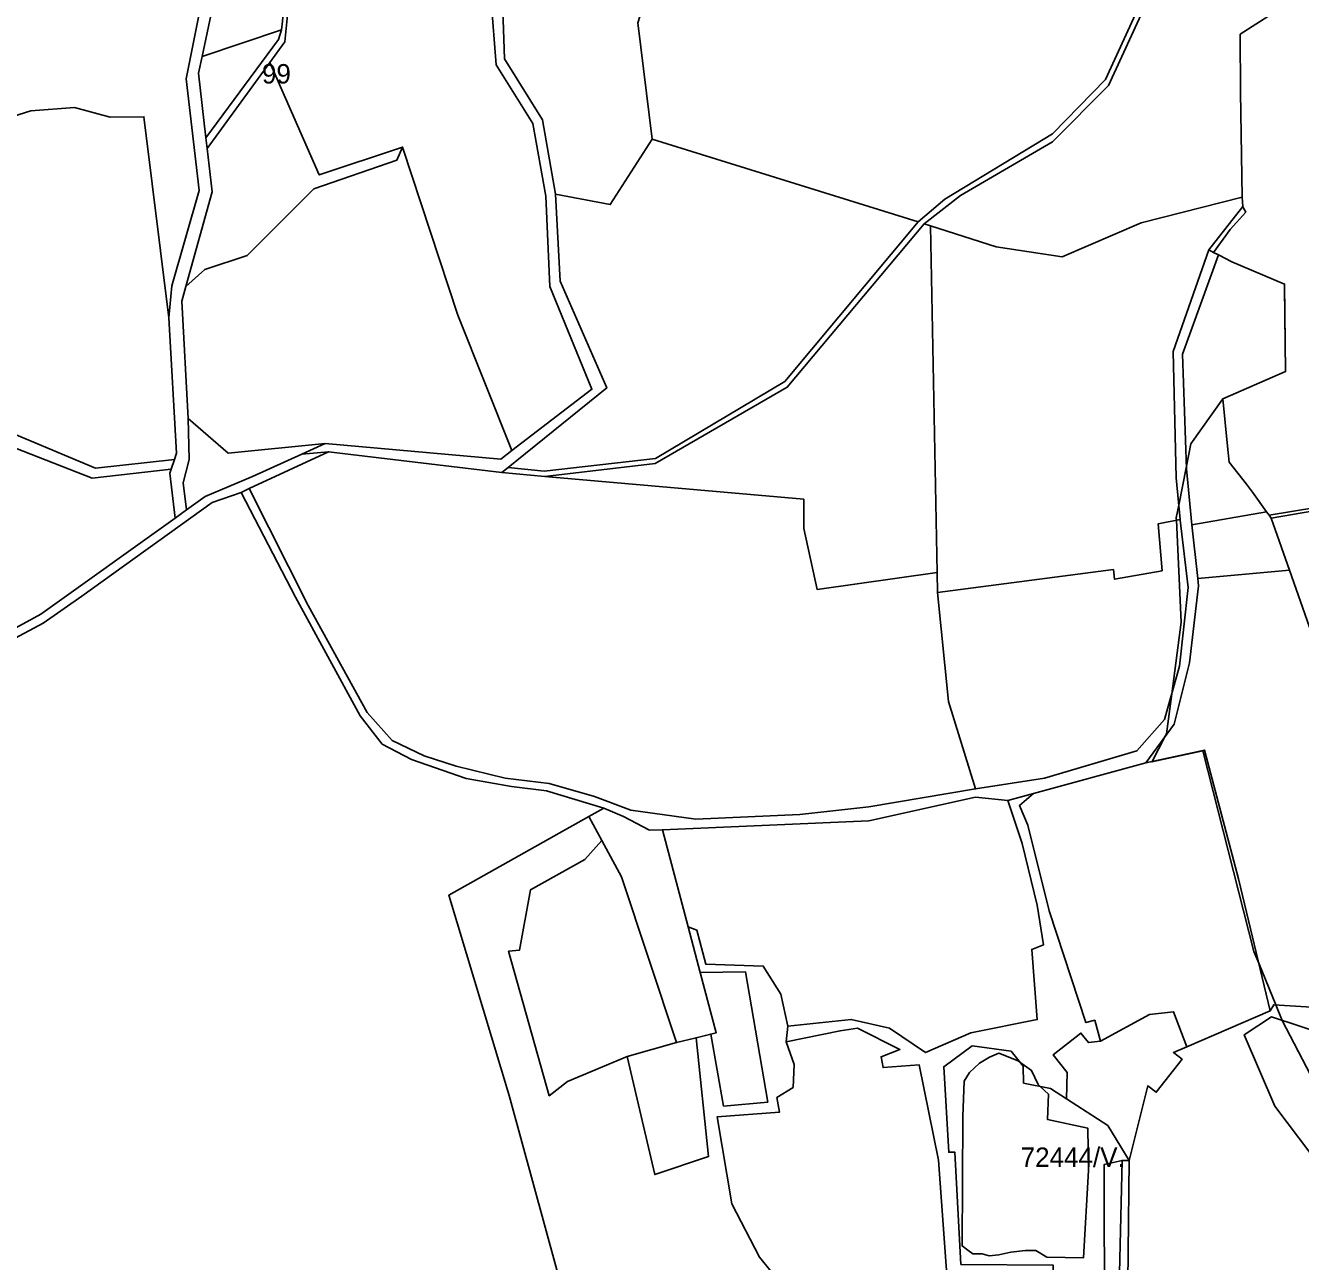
# Model space of a CAD drawing. Extents: x -502026 to -497664, y -1143484 to -1138019.
# Drawn here: x -499334 to -498809, y -1143009 to -1142500 of the extents above; entities that cross this region are included whole.
import ezdxf

# ---------------------------------------------------------------- set-up
doc = ezdxf.new("R2010")
doc.units = 0
for name, color, linetype in [('37', 7, 'Continuous'), ('43', 7, 'Continuous'), ('55', 7, 'Continuous'), ('62', 7, 'Continuous')]:
    doc.layers.add(name, color=color, linetype=linetype)

msp = doc.modelspace()

# ---------------------------------------------------------------- linework, layer by layer
at = {"layer": '37'}
msp.add_lwpolyline([(-498718.92, -1142695.09), (-498713.81, -1142703.58), (-498705.09, -1142704.42), (-498696.25, -1142725.42), (-498729.58, -1142732.34), (-498768.81, -1142745.89), (-498802.13, -1142758.2), (-498813.95, -1142724.49), (-498821.39, -1142703.09), (-498781.57, -1142696.34), (-498742.86, -1142693.2)], close=True, dxfattribs=at)
at = {"layer": '43'}
for points in [[(-499186.12, -1142301.39), (-499193.9, -1142349.92), (-499212.53, -1142388.21), (-499216.16, -1142395.67), (-499227.31, -1142507.01), (-499233.5, -1142515.51), (-499259.3, -1142550.94), (-499259.79, -1142546.61), (-499229.88, -1142506.05), (-499228.62, -1142502.13), (-499228.3, -1142498.46), (-499219.13, -1142394.71), (-499215.59, -1142387.65), (-499195.99, -1142348.47), (-499191.48, -1142319.08), (-499188.68, -1142300.88)], [(-499063.88, -1142441.35), (-499082.12, -1142499.27), (-499076.16, -1142547.04), (-499093.38, -1142574.06), (-499115.92, -1142569.72), (-499121.25, -1142539.11), (-499136.98, -1142514.08), (-499138.35, -1142473.56), (-499129.3, -1142435.22)], [(-499259.79, -1142546.61), (-499262.83, -1142519.94), (-499261.37, -1142513.05), (-499228.62, -1142502.13), (-499229.88, -1142506.05)], [(-499178.85, -1142550.33), (-499181.2, -1142555.78), (-499215.39, -1142567.55), (-499242.77, -1142595.06), (-499260.23, -1142600.76), (-499268.02, -1142607.75), (-499257.26, -1142568.79), (-499259.3, -1142550.94), (-499233.5, -1142515.51), (-499213.16, -1142561.85)], [(-498966.7, -1142581.15), (-499021.62, -1142646.92), (-499074.76, -1142678.52), (-499120.59, -1142683.79), (-499135.36, -1142682.28), (-499094.83, -1142649.52), (-499114.07, -1142605.54), (-499115.92, -1142569.72), (-499093.38, -1142574.06), (-499076.16, -1142547.04)], [(-499133.88, -1142675.3), (-499138.47, -1142678.81), (-499210.68, -1142672.39), (-499250.66, -1142676.39), (-499267.09, -1142662.15), (-499269.7, -1142613.84), (-499268.02, -1142607.75), (-499260.23, -1142600.76), (-499242.77, -1142595.06), (-499215.39, -1142567.55), (-499181.2, -1142555.78), (-499178.85, -1142550.33), (-499156.06, -1142619.54)], [(-498833.12, -1142574.8), (-498847.11, -1142592.66), (-498861.74, -1142634.49), (-498860.56, -1142686.49), (-498858.93, -1142703.74), (-498867.93, -1142705.43), (-498866.32, -1142724.83), (-498885.89, -1142728.3), (-498886.33, -1142724.35), (-498958.76, -1142733.81), (-498958.86, -1142725.52), (-498961.6, -1142582.77), (-498934.61, -1142591.49), (-498907.39, -1142595.5), (-498874.99, -1142581.57), (-498833.33, -1142570.94)], [(-498961.6, -1142582.77), (-498958.86, -1142725.52), (-499008.31, -1142732.5), (-499013.79, -1142707.36), (-499013.79, -1142695.36), (-499120.39, -1142685.99), (-499074.92, -1142680.62), (-499020.57, -1142649.24), (-498964.28, -1142581.91)], [(-498823.31, -1142700.5), (-498854.02, -1142705.83), (-498856.28, -1142682.79), (-498857.89, -1142635.65), (-498843.16, -1142594.79), (-498837.62, -1142597.55), (-498815.89, -1142606.77), (-498815.49, -1142642.8), (-498841.37, -1142654.07), (-498839.34, -1142673.46), (-498838.65, -1142680.03), (-498831.61, -1142689.17), (-498829.05, -1142692.5)], [(-499210.68, -1142672.39), (-499220.38, -1142676.8), (-499240.61, -1142685.99), (-499260.08, -1142694.22), (-499267.81, -1142699.76), (-499269.13, -1142688.66), (-499266.62, -1142679.06), (-499267.09, -1142662.15), (-499250.66, -1142676.39)], [(-499274.07, -1142683.02), (-499274.62, -1142684.66), (-499272.44, -1142703.08), (-499327.73, -1142742.72), (-499360.83, -1142760.7), (-499390.53, -1142787.67), (-499419.09, -1142808.73), (-499455.39, -1142717), (-499437.6, -1142711.34), (-499398.67, -1142683.09), (-499357.32, -1142673.8), (-499341.27, -1142673.06), (-499306.6, -1142686.61)], [(-499137.98, -1142684.28), (-499120.39, -1142685.99), (-499013.79, -1142695.36), (-499013.79, -1142707.36), (-499008.31, -1142732.5), (-498958.86, -1142725.52), (-498958.76, -1142733.81), (-498954.16, -1142778.67), (-498943.09, -1142814.6), (-498986.95, -1142821.98), (-499015.32, -1142825.12), (-499058.16, -1142827.09), (-499084.93, -1142823.39), (-499099.91, -1142817.8), (-499118.5, -1142812.36), (-499136.71, -1142810.13), (-499156.79, -1142805.27), (-499170.03, -1142800.96), (-499183.16, -1142794.64), (-499193.44, -1142783.11), (-499217.78, -1142739.04), (-499242.02, -1142690.97), (-499209.32, -1142675.8)], [(-498943.09, -1142814.6), (-498954.16, -1142778.67), (-498958.76, -1142733.81), (-498886.33, -1142724.35), (-498885.89, -1142728.3), (-498866.32, -1142724.83), (-498867.93, -1142705.43), (-498858.93, -1142703.74), (-498858.92, -1142703.91), (-498855.63, -1142731.69), (-498859.19, -1142764.04), (-498865.29, -1142786.09), (-498876.67, -1142799.01), (-498914.66, -1142810.14)], [(-498822.28, -1142701.93), (-498821.39, -1142703.09), (-498813.95, -1142724.49), (-498851.63, -1142727.92), (-498854.02, -1142705.83), (-498823.31, -1142700.5)], [(-498802.13, -1142758.2), (-498801.6, -1142759.91), (-498804.77, -1142761.15), (-498804.49, -1142762.6), (-498798.94, -1142790.97), (-498797.52, -1142794.75), (-498793.96, -1142803.22), (-498792.37, -1142807.01), (-498789.64, -1142827.96), (-498780.24, -1142890.32), (-498780.62, -1142901.94), (-498800.33, -1142904.75), (-498820.36, -1142903.49), (-498821.78, -1142906.01), (-498834.84, -1142851.68), (-498848.87, -1142798.61), (-498873.05, -1142803.85), (-498861.35, -1142788.01), (-498855.04, -1142762.74), (-498851.29, -1142731.06), (-498851.63, -1142727.92), (-498813.95, -1142724.49)], [(-498821.78, -1142906.01), (-498856.2, -1142920.76), (-498861.62, -1142906.39), (-498871.46, -1142907.52), (-498891.69, -1142918.55), (-498894.02, -1142909.9), (-498897.63, -1142910.86), (-498912.8, -1142864.76), (-498921.5, -1142829.55), (-498925.04, -1142821.48), (-498919.17, -1142816.54), (-498873.05, -1142803.85), (-498848.87, -1142798.61), (-498834.84, -1142851.68)], [(-498929.8, -1142819.46), (-498923.87, -1142837.05), (-498917.77, -1142862.47), (-498915.09, -1142878.85), (-498919.94, -1142880.69), (-498917.69, -1142909.62), (-498945.06, -1142915.09), (-498963.74, -1142923.17), (-498978.52, -1142913.19), (-498994.26, -1142909.54), (-499020.31, -1142912.27), (-499023.15, -1142899.13), (-499030.46, -1142887.55), (-499054.13, -1142886.82), (-499057.74, -1142872.74), (-499061.34, -1142871.38), (-499071.91, -1142831.44), (-498987, -1142827.81), (-498943.09, -1142818.07)], [(-499071.91, -1142831.44), (-499061.34, -1142871.38), (-499056.35, -1142890.25), (-499049.79, -1142915.04), (-499052.02, -1142915.59), (-499058.09, -1142917.09), (-499066.15, -1142919.07), (-499088.81, -1142850.86), (-499096.86, -1142835.91), (-499102.19, -1142826.02), (-499096.01, -1142822.55), (-499087.9, -1142825.99), (-499077.3, -1142831.66)], [(-499066.15, -1142919.07), (-499086.46, -1142924.75), (-499110.93, -1142935.08), (-499118.52, -1142940.96), (-499135.24, -1142881.44), (-499130.78, -1142881.04), (-499126.22, -1142856.13), (-499103.89, -1142843.73), (-499096.86, -1142835.91), (-499088.81, -1142850.86)], [(-499052.02, -1142915.59), (-499049.79, -1142915.04), (-499056.35, -1142890.25), (-499037.77, -1142889.87), (-499028.6, -1142943.57), (-499046.78, -1142945.23)], [(-498856.2, -1142920.76), (-498861.68, -1142923.11), (-498858.09, -1142925.91), (-498868.71, -1142939.54), (-498872.18, -1142936.84), (-498879.9, -1142967.62), (-498888.66, -1142953.18), (-498905.65, -1142942.19), (-498905.43, -1142931.44), (-498911.17, -1142924.16), (-498899.72, -1142915.13), (-498896.61, -1142919.07), (-498891.69, -1142918.55), (-498871.46, -1142907.52), (-498861.62, -1142906.39)], [(-498787.24, -1142934.61), (-498791.45, -1142942.27), (-498794.1, -1142951.32), (-498787.26, -1142964.11), (-498768.58, -1142992.66), (-498775.87, -1143002.39), (-498784.58, -1142992.53), (-498790.85, -1142993.81), (-498800.06, -1142971.66), (-498819.9, -1142945.25), (-498832.51, -1142915.83), (-498821.31, -1142908.5), (-498799.17, -1142915.67), (-498794.56, -1142926.55)], [(-498978.38, -1143067.64), (-498985.62, -1143037.13), (-499006.08, -1143039.33), (-499008.67, -1143036.14), (-499031.92, -1143007.46), (-499043.31, -1142985.4), (-499049.39, -1142949.62), (-499023.78, -1142947.73), (-499024.81, -1142941.68), (-499018.17, -1142937.49), (-499017.78, -1142928.08), (-499021.01, -1142918.81), (-498998.8, -1142914.2), (-498991.7, -1142913.18), (-498974.23, -1142921.89), (-498981.94, -1142924.88), (-498981.14, -1142929.36), (-498966.23, -1142928.26), (-498958.26, -1142967.52), (-498953.28, -1143037.42), (-498969.24, -1143059.9)], [(-499086.46, -1142924.75), (-499066.15, -1142919.07), (-499058.09, -1142917.09), (-499052.95, -1142965.98), (-499075.08, -1142973.42)], [(-498905.65, -1142942.19), (-498888.66, -1142953.18), (-498879.9, -1142967.62), (-498882.81, -1142967.59), (-498890.11, -1142969.25), (-498890.07, -1143037.19), (-498911.43, -1143041.96), (-498911.18, -1143010.7), (-498949.07, -1143010.39), (-498951.56, -1142964.2), (-498954.14, -1142964.19), (-498956.19, -1142928.99), (-498944.46, -1142920.41), (-498928.45, -1142922.62), (-498923.55, -1142928.78), (-498923.32, -1142935.75), (-498912.27, -1142937.91)], [(-498879.9, -1142967.62), (-498880.64, -1143042.87), (-498876.46, -1143077.46), (-498889.09, -1143081.57), (-498897.61, -1143079.07), (-498898.74, -1143044.93), (-498884.54, -1143042.85), (-498882.81, -1142967.59)]]:
    msp.add_lwpolyline(points, close=True, dxfattribs=at)
for points in [[(-499143.8, -1142472.44), (-499140.33, -1142516.56), (-499125.21, -1142540.6), (-499119.89, -1142570.59), (-499118.28, -1142607.77), (-499100.94, -1142650.06), (-499133.88, -1142675.3), (-499156.06, -1142619.54), (-499178.85, -1142550.33), (-499213.16, -1142561.85), (-499233.5, -1142515.51), (-499227.31, -1142507.01), (-499216.16, -1142395.67)], [(-499255.77, -1142460.92), (-499267.85, -1142522.22), (-499262.59, -1142568.19), (-499273.82, -1142607.44), (-499275.01, -1142620.71), (-499285.33, -1142537.9), (-499299.13, -1142538.05), (-499313.87, -1142534.09), (-499331.89, -1142535.47), (-499383.94, -1142551.77)], [(-499228.3, -1142498.46), (-499228.62, -1142502.13), (-499261.37, -1142513.05), (-499250.45, -1142461.57)], [(-498866.58, -1142472.13), (-498889.62, -1142522.6), (-498911.44, -1142544.84), (-498955.78, -1142571.85), (-498966.7, -1142581.15), (-499076.16, -1142547.04), (-499082.12, -1142499.27)], [(-498814.79, -1142491.58), (-498834.12, -1142503.88), (-498834.03, -1142527.73), (-498833.33, -1142570.94), (-498874.99, -1142581.57), (-498907.39, -1142595.5), (-498934.61, -1142591.49), (-498961.6, -1142582.77), (-498964.28, -1142581.91), (-498949.34, -1142570.24), (-498911.44, -1142548.18), (-498888.32, -1142524.95), (-498863.98, -1142471.76)], [(-499383.94, -1142551.77), (-499331.89, -1142535.47), (-499313.87, -1142534.09), (-499299.13, -1142538.05), (-499285.33, -1142537.9), (-499275.01, -1142620.71), (-499271.87, -1142676.44), (-499272.71, -1142678.95), (-499305.23, -1142682.61), (-499341.21, -1142667.43)], [(-499357.89, -1142763.04), (-499326.71, -1142746.41), (-499310.8, -1142735.23), (-499257.26, -1142696.67), (-499245.27, -1142692.58), (-499222.99, -1142735.63), (-499196.34, -1142784.58), (-499187.21, -1142796.15), (-499175.15, -1142802.55), (-499152.7, -1142810.27), (-499134.05, -1142813.56), (-499119.61, -1142815.39), (-499096.01, -1142822.55), (-499102.19, -1142826.02), (-499159.82, -1142858.36), (-499135.06, -1142940.83), (-499101.04, -1143065.28)], [(-498953.28, -1143037.42), (-498958.26, -1142967.52), (-498966.23, -1142928.26), (-498981.14, -1142929.36), (-498981.94, -1142924.88), (-498974.23, -1142921.89), (-498991.7, -1142913.18), (-498998.8, -1142914.2), (-499021.01, -1142918.81), (-499020.31, -1142912.27), (-498994.26, -1142909.54), (-498978.52, -1142913.19), (-498963.74, -1142923.17), (-498945.06, -1142915.09), (-498917.69, -1142909.62), (-498919.94, -1142880.69), (-498915.09, -1142878.85), (-498917.77, -1142862.47), (-498923.87, -1142837.05), (-498929.8, -1142819.46), (-498919.17, -1142816.54), (-498925.04, -1142821.48), (-498921.5, -1142829.55), (-498912.8, -1142864.76), (-498897.63, -1142910.86), (-498894.02, -1142909.9), (-498891.69, -1142918.55), (-498896.61, -1142919.07), (-498899.72, -1142915.13), (-498911.17, -1142924.16), (-498905.43, -1142931.44), (-498905.65, -1142942.19), (-498912.27, -1142937.91), (-498923.32, -1142935.75), (-498923.55, -1142928.78), (-498928.45, -1142922.62), (-498944.46, -1142920.41), (-498956.19, -1142928.99), (-498954.14, -1142964.19), (-498951.56, -1142964.2), (-498949.07, -1143010.39)], [(-499101.04, -1143065.28), (-499135.06, -1142940.83), (-499159.82, -1142858.36), (-499102.19, -1142826.02), (-499096.86, -1142835.91), (-499103.89, -1142843.73), (-499126.22, -1142856.13), (-499130.78, -1142881.04), (-499135.24, -1142881.44), (-499118.52, -1142940.96), (-499110.93, -1142935.08), (-499086.46, -1142924.75), (-499075.08, -1142973.42), (-499052.95, -1142965.98), (-499058.09, -1142917.09), (-499052.02, -1142915.59), (-499046.78, -1142945.23), (-499028.6, -1142943.57), (-499037.77, -1142889.87), (-499056.35, -1142890.25), (-499061.34, -1142871.38), (-499057.74, -1142872.74), (-499054.13, -1142886.82), (-499030.46, -1142887.55), (-499023.15, -1142899.13), (-499020.31, -1142912.27), (-499021.01, -1142918.81), (-499017.78, -1142928.08), (-499018.17, -1142937.49), (-499024.81, -1142941.68), (-499023.78, -1142947.73), (-499049.39, -1142949.62), (-499043.31, -1142985.4), (-499031.92, -1143007.46), (-499008.67, -1143036.14)], [(-498880.64, -1143042.87), (-498879.9, -1142967.62), (-498872.18, -1142936.84), (-498868.71, -1142939.54), (-498858.09, -1142925.91), (-498861.68, -1142923.11), (-498856.2, -1142920.76), (-498821.78, -1142906.01), (-498820.36, -1142903.49), (-498800.33, -1142904.75)], [(-498799.17, -1142915.67), (-498821.31, -1142908.5), (-498832.51, -1142915.83), (-498819.9, -1142945.25), (-498800.06, -1142971.66)], [(-498890.07, -1143037.19), (-498890.11, -1142969.25), (-498882.81, -1142967.59), (-498884.54, -1143042.85)]]:
    msp.add_lwpolyline(points, dxfattribs=at)
at = {"layer": '55'}
for points in [[(-499250.45, -1142461.57), (-499261.37, -1142513.05), (-499262.83, -1142519.94), (-499259.79, -1142546.61), (-499259.3, -1142550.94), (-499257.26, -1142568.79), (-499268.02, -1142607.75), (-499269.7, -1142613.84), (-499267.09, -1142662.15), (-499266.62, -1142679.06), (-499269.13, -1142688.66), (-499267.81, -1142699.76), (-499272.44, -1142703.08), (-499274.62, -1142684.66), (-499274.07, -1142683.02), (-499272.71, -1142678.95), (-499271.87, -1142676.44), (-499275.01, -1142620.71), (-499273.82, -1142607.44), (-499262.59, -1142568.19), (-499267.85, -1142522.22), (-499255.77, -1142460.92)], [(-499138.35, -1142473.56), (-499136.98, -1142514.08), (-499121.25, -1142539.11), (-499115.92, -1142569.72), (-499114.07, -1142605.54), (-499094.83, -1142649.52), (-499135.36, -1142682.28), (-499137.98, -1142684.28), (-499209.32, -1142675.8), (-499220.38, -1142676.8), (-499210.68, -1142672.39), (-499138.47, -1142678.81), (-499133.88, -1142675.3), (-499100.94, -1142650.06), (-499118.28, -1142607.77), (-499119.89, -1142570.59), (-499125.21, -1142540.6), (-499140.33, -1142516.56), (-499143.8, -1142472.44)], [(-498863.98, -1142471.76), (-498888.32, -1142524.95), (-498911.44, -1142548.18), (-498949.34, -1142570.24), (-498964.28, -1142581.91), (-499020.57, -1142649.24), (-499074.92, -1142680.62), (-499120.39, -1142685.99), (-499137.98, -1142684.28), (-499135.36, -1142682.28), (-499120.59, -1142683.79), (-499074.76, -1142678.52), (-499021.62, -1142646.92), (-498966.7, -1142581.15), (-498955.78, -1142571.85), (-498911.44, -1142544.84), (-498889.62, -1142522.6), (-498866.58, -1142472.13)], [(-499341.21, -1142667.43), (-499305.23, -1142682.61), (-499272.71, -1142678.95), (-499274.07, -1142683.02), (-499306.6, -1142686.61), (-499341.27, -1142673.06)], [(-499360.83, -1142760.7), (-499327.73, -1142742.72), (-499272.44, -1142703.08), (-499267.81, -1142699.76), (-499260.08, -1142694.22), (-499240.61, -1142685.99), (-499220.38, -1142676.8), (-499209.32, -1142675.8), (-499242.02, -1142690.97), (-499245.27, -1142692.58), (-499257.26, -1142696.67), (-499310.8, -1142735.23), (-499326.71, -1142746.41), (-499357.89, -1142763.04)]]:
    msp.add_lwpolyline(points, dxfattribs=at)
for points in [[(-498845.21, -1142593.77), (-498847.11, -1142592.66), (-498833.12, -1142574.8), (-498832.91, -1142575.2), (-498831.91, -1142577.12), (-498838.27, -1142584.27)], [(-498845.21, -1142593.77), (-498843.16, -1142594.79), (-498857.89, -1142635.65), (-498856.28, -1142682.79), (-498854.02, -1142705.83), (-498851.63, -1142727.92), (-498851.29, -1142731.06), (-498855.04, -1142762.74), (-498861.35, -1142788.01), (-498873.05, -1142803.85), (-498919.17, -1142816.54), (-498929.8, -1142819.46), (-498943.09, -1142818.07), (-498987, -1142827.81), (-499071.91, -1142831.44), (-499077.3, -1142831.66), (-499087.9, -1142825.99), (-499096.01, -1142822.55), (-499119.61, -1142815.39), (-499134.05, -1142813.56), (-499152.7, -1142810.27), (-499175.15, -1142802.55), (-499187.21, -1142796.15), (-499196.34, -1142784.58), (-499222.99, -1142735.63), (-499245.27, -1142692.58), (-499242.02, -1142690.97), (-499217.78, -1142739.04), (-499193.44, -1142783.11), (-499183.16, -1142794.64), (-499170.03, -1142800.96), (-499156.79, -1142805.27), (-499136.71, -1142810.13), (-499118.5, -1142812.36), (-499099.91, -1142817.8), (-499084.93, -1142823.39), (-499058.16, -1142827.09), (-499015.32, -1142825.12), (-498986.95, -1142821.98), (-498943.09, -1142814.6), (-498914.66, -1142810.14), (-498876.67, -1142799.01), (-498865.29, -1142786.09), (-498859.19, -1142764.04), (-498855.63, -1142731.69), (-498858.92, -1142703.91), (-498858.93, -1142703.74), (-498860.56, -1142686.49), (-498861.74, -1142634.49), (-498847.11, -1142592.66)], [(-498549.19, -1142729.61), (-498574.36, -1142721.48), (-498608.31, -1142711.62), (-498634.43, -1142703.56), (-498668.99, -1142697.77), (-498705.26, -1142696.31), (-498718.92, -1142695.09), (-498742.86, -1142693.2), (-498781.57, -1142696.34), (-498821.39, -1142703.09), (-498822.28, -1142701.93), (-498783.08, -1142695.45), (-498762.56, -1142693.69), (-498743.39, -1142692.1), (-498707.76, -1142694.47), (-498691.29, -1142695.25), (-498668.23, -1142696.44), (-498646.3, -1142699.53), (-498632.79, -1142702.37), (-498619.48, -1142705.38), (-498603.94, -1142709.81), (-498571.77, -1142720.19), (-498550.49, -1142727.91), (-498549.47, -1142728.28)]]:
    msp.add_lwpolyline(points, close=True, dxfattribs=at)
at = {"layer": '62'}
for points in [[(-498814.79, -1142491.58), (-498834.12, -1142503.88), (-498834.03, -1142527.73), (-498833.33, -1142570.94), (-498833.12, -1142574.8), (-498832.91, -1142575.2), (-498831.91, -1142577.12), (-498838.27, -1142584.27), (-498845.21, -1142593.77), (-498843.16, -1142594.79), (-498837.62, -1142597.55), (-498815.89, -1142606.77), (-498815.88, -1142608.03), (-498815.49, -1142642.8), (-498841.37, -1142654.07), (-498854.5, -1142672.5), (-498856.32, -1142681.73), (-498859.49, -1142697.85), (-498860.5, -1142703), (-498860.45, -1142704.02), (-498858.5, -1142746), (-498862.34, -1142775.41), (-498864.5, -1142792), (-498864.99, -1142792.93), (-498870.38, -1142803.27), (-498870.5, -1142803.5), (-498849.5, -1142799), (-498828.5, -1142881.5), (-498826.49, -1142886.4), (-498819.47, -1142903.54), (-498816.85, -1142909.94), (-498805.26, -1142932.33)], [(-498805.26, -1142932.33), (-498816.85, -1142909.94), (-498819.47, -1142903.54), (-498826.49, -1142886.4), (-498828.5, -1142881.5), (-498849.5, -1142799), (-498870.5, -1142803.5), (-498870.38, -1142803.27), (-498864.99, -1142792.93), (-498864.5, -1142792), (-498862.34, -1142775.41), (-498858.5, -1142746), (-498860.45, -1142704.02), (-498860.5, -1142703), (-498859.49, -1142697.85), (-498856.32, -1142681.73), (-498854.5, -1142672.5), (-498841.37, -1142654.07), (-498839.34, -1142673.46), (-498838.65, -1142680.03), (-498831.61, -1142689.17), (-498829.05, -1142692.5), (-498823.31, -1142700.5), (-498822.28, -1142701.93), (-498783.08, -1142695.45)]]:
    msp.add_lwpolyline(points, dxfattribs=at)
for points in [[(-498896.6, -1142971.8), (-498898.7, -1143007.7), (-498913.7, -1143007.4), (-498918.3, -1143004.7), (-498922.5, -1143004.7), (-498928.5, -1143005.3), (-498933.5, -1143006.4), (-498937.5, -1143006.8), (-498940.31, -1143006.08), (-498944.2, -1143006), (-498946.3, -1143004.5), (-498948.6, -1143002.8), (-498948.3, -1142949.5), (-498947.7, -1142934.9), (-498945.6, -1142931.4), (-498941.5, -1142927.6), (-498937.3, -1142925.1), (-498933.5, -1142923.4), (-498925.6, -1142926.6), (-498924.89, -1142927.09), (-498920, -1142930.5), (-498917.3, -1142936.3), (-498916.44, -1142937.09), (-498913.03, -1142940.26), (-498913.5, -1142950.7), (-498896.9, -1142954.3)], [(-498896.6, -1142971.8), (-498896.9, -1142954.3), (-498913.5, -1142950.7), (-498913.03, -1142940.26), (-498916.44, -1142937.09), (-498917.3, -1142936.3), (-498920, -1142930.5), (-498924.89, -1142927.09), (-498925.6, -1142926.6), (-498933.5, -1142923.4), (-498937.3, -1142925.1), (-498941.5, -1142927.6), (-498945.6, -1142931.4), (-498947.7, -1142934.9), (-498948.3, -1142949.5), (-498948.6, -1143002.8), (-498946.3, -1143004.5), (-498944.2, -1143006), (-498940.31, -1143006.08), (-498937.5, -1143006.8), (-498933.5, -1143006.4), (-498928.5, -1143005.3), (-498922.5, -1143004.7), (-498918.3, -1143004.7), (-498913.7, -1143007.4), (-498898.7, -1143007.7)]]:
    msp.add_lwpolyline(points, close=True, dxfattribs=at)

# ---------------------------------------------------------------- texts
for s, p in [('99', (-499236.73, -1142524.19)), ('72444/V.', (-498924.51, -1142970.26))]:
    msp.add_text(s, height=8, dxfattribs=at).set_placement(p)

doc.saveas('drawing.dxf')
